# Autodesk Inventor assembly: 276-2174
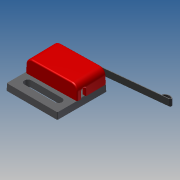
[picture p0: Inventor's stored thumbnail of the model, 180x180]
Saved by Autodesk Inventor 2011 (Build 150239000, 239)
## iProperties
Company: Autodesk Inc.
Created: 2010-05
Part Number: 276-2174
Document SubType Name: Assembly
Designer: Autodesk Inc.
Catalog Web Link: http://www.vexrobotics.com/276-2174.html
Vendor: Innovation First, Inc.
Author: Autodesk Inc.
Title: VEX Robotics Kit of Parts
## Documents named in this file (4)
- C:\Data Folder\VEX KOP 2010\VEX Parts Kit\Sensors\Limit Switch.iam
- C:\Data Folder\VEX KOP 2010\VEX Parts Kit\Sensors\Limit Switch Microswitch.ipt
- C:\Data Folder\VEX KOP 2010\VEX Parts Kit\Sensors\Limit Switch Bottom.ipt
- C:\Data Folder\VEX KOP 2010\VEX Parts Kit\Sensors\Limit_Switch_Top.ipt
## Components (3 placed, 3 different names)
1. Limit Switch Microswitch:1 — Mate:1, Mate:2, Mate:3
2. Limit Switch Bottom:1 — Mate:1, Mate:2, Mate:3, Mate:4, Mate:5
3. Limit_Switch_Top:1 — Mate:4, Mate:5
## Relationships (5: Mate 5)
- Mate:1: Limit Switch Microswitch:1 ↔ Limit Switch Bottom:1
- Mate:2: Limit Switch Microswitch:1 ↔ Limit Switch Bottom:1
- Mate:3: Limit Switch Microswitch:1 ↔ Limit Switch Bottom:1
- Mate:4: Limit Switch Bottom:1 ↔ Limit_Switch_Top:1
- Mate:5: Limit Switch Bottom:1 ↔ Limit_Switch_Top:1
